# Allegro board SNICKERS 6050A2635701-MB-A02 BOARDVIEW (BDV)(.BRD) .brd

Outline 330.05 x 164 mm; copper layers: TOP, L2, L3, L4, L5, L6, L7, BOTTOM. Coordinates in mm from the lower left corner of the outline.

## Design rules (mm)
net group 3V3DS_PG: nets 3V3DS_PG UNNAMED_17_CSC0402_I437_A
net group 4-20: nets CL_RST#1 THRMTRIP#
net group 10-10: nets DMIC_CLK DMIC_DAT
net group 8051_TX_LED_PWRSTBY#: nets 8051_TX_LED_PWRSTBY# LED_PWRSTBY#
net group ADP_PRES: nets UNNAMED_5_BQ24736RGRR_I30_CMSRC UNNAMED_6_COMPARATOR_I63_1
net group AMP_PD: nets AMP_PD UNNAMED_54_DB3X313J0L_I631_2
net group APWROK: nets APWROK PCH_PWROK
net group AZ_R3S_SDOUT: nets HDA_SDO_R UNNAMED_27_NMOS_I61_S
net group BAT_GRNLED#: nets BAT_GRNLED# UNNAMED_27_LBSS84LT1G_I270_G
net group CFG<3>: nets CFG<3> MSR_ENABLE_N
net group CLK_PCIE3_D: nets CLK_PCIE3_DN CLK_PCIE3_DP
net group CLK_R3S_DEBUG: nets CLK_R3S_TPM CLK_TPM_DEBUG
net group CPPWR_EN: nets CPPWR_EN UNNAMED_41_RSC0402_I206_A
net group CRT_HSYNC: nets CRT_HSYNC CRT_HSYNC_R
net group CRT_VSYNC: nets CRT_VSYNC CRT_VSYNC_R
net group DDR_PG_CTRL: nets DDR_PG_CTRL UNNAMED_32_NPNB_I568_B
net group DDR_WR_VREF01: nets DDR_WR_VREF01 UNNAMED_25_CSC0402_I269_B
net group DDR_WR_VREF02: nets DDR_WR_VREF02 UNNAMED_25_CSC0402_I270_B
net group DGND_PBN: nets P3V3AL_PB UNNAMED_57_LEDSINGLE_I235_A2
net group DP1: nets DPC_DOCK_CLK_AUX_DP DPC_DOCK_DATA_AUX_DN
net group DPB2_DOCK_D: nets DPB2_DOCK_DN DPB2_DOCK_DP
net group DPB3_DOCK_D: nets DPB3_DOCK_DN DPB3_DOCK_DP
net group DPC0_DOCK_D: nets DPC0_DOCK_DN DPC0_DOCK_DP
net group DPC1_DOCK_D: nets DPC1_DOCK_DN DPC1_DOCK_DP
net group EN_1V2A: nets EN_1V2A SLP_S4#_3R
net group FPR_OFF: nets FPR_OFF FPR_OFF_GPIO11
net group GPU_THRM_DMINUS: nets GPU_THRM_DMINUS GPU_THRM_DPLUS
net group HDD_HALTLED: nets HDD_HALTLED HDD_HALTLED_R
net group HP_AMP_PD#: nets HP_AMP_PD# UNNAMED_54_NMOS_I641_D
net group HP_OUT_L1: nets UNNAMED_55_CSC0402_I514_A UNNAMED_55_HPA022642RTJ_I496_LE
net group HP_OUT_R1: nets UNNAMED_55_CSC0402_I529_A UNNAMED_55_HPA022642RTJ_I496_RI
net group HUB_XTAL_IN: nets HUB_XTAL_IN HUB_XTAL_OUT
net group ISO_PREP#: nets ISO_PREP# UNNAMED_26_CL8064701477702SR170
net group LAN_DIS#: nets LAN_DIS# UNNAMED_49_NPND_I463_B
net group LED_3S_LANACT#: nets LED_3S_LANACT# UNNAMED_49_I218LM_I128_27
net group LED_3S_LANLINK#: nets LED_3S_LANLINK# LED_3S_LANLINK#_R
net group LINE_OUT_DET: nets LINE_OUT_DET UNNAMED_54_ALC3228CG_I513_SEN_1
net group LVDS_VDD_EN: nets LVDS_VDD_EN UNNAMED_38_CN404G_I622_6
net group MAIN_BAT_DET#: nets MAIN_BAT_DET# UNNAMED_16_BP02083B24B19H_I11_2
net group MSATA_DET#: nets MSATA_DET# UNNAMED_40_APCI0020P001A01_I3_2
net group NUM_LOCK_LED#: nets NUM_LOCK_LED# UNNAMED_47_CN342G_I454_5
net group ON_OFF#1: nets ON_OFF#1 PWRBTN#
net group P3V3S_SM_AB: nets P3V3S_SM_AB UNNAMED_58_AU9542B55GBSGR_I52_1
net group P3V3S_SSD: nets P3V3S_SSD UNNAMED_40_APCI0020P001A01_I375
net group P5V0DS_SM: nets P5V0S_SM UNNAMED_58_CN152G_I567_12
net group PCIE_RX6_L0_C_D: nets PCIE_RX6_L0_C_DN PCIE_RX6_L0_C_DP
net group PM_SLP_A#: nets PM_SLP_A# UNNAMED_18_DB3X313J0L_I216_1
net group PR_AOUT_L_DOCK: nets PR_AOUT_L_DOCK UNNAMED_55_HPA022642RTJ_I457_HP
net group PR_AOUT_R_DOCK: nets PR_AOUT_R_DOCK UNNAMED_55_HPA022642RTJ_I457__1
net group PVSIM: nets UNNAMED_51_APCI0018P005A_I342_F WWAN_NGFF_DPR
net group PVT_MOSI: nets PVT_MOSI UNNAMED_46_MECC1322NU_I1013_GPI
net group R_SPI_WP#: nets R_SPI_WP# SPI_WP#
net group REC_MUTE_LED: nets REC_MUTE_LED UNNAMED_47_CN342G_I454_2
net group RSMRST#: nets RSMRST# UNNAMED_46_MECC1322NU_I1013_G_2
net group SCAN_3S_IN: nets SCAN_3S_IN<4> SCAN_3S_IN<7>
net group SCAN_3S_IN<0>: nets SCAN_3S_IN<0> SCAN_3S_IN<1>
net group SCAN_3S_IN<2>: nets SCAN_3S_IN<2> SCAN_3S_IN<3>
net group SCAN_3S_IN<5>: nets SCAN_3S_IN<5> SCAN_3S_IN<6>
net group SCAN_3S_OUT<1>: nets SCAN_3S_OUT<1> SPI_CS0#_FLH_R6_R
net group SCAN_3S_OUT<2>: nets SCAN_3S_OUT<2> SPI_SO_FLH_R6_R
net group SCAN_3S_OUT<3>: nets SCAN_3S_OUT<3> SPI_SI_FLH_R6_R
net group SCL_BAT_CHG: nets SCL_BAT_CHG UNNAMED_16_BP02083B24B19H_I11_1
net group SDA_BAT_CHG: nets SDA_BAT_CHG UNNAMED_16_BP02083B24B19H_I112_
net group UIM_CD: nets UIM_CD UIM_DATA
net group UNNAMED_5_BQ24736RGRR_I30_ACDRV: nets UNNAMED_5_BQ24736RGRR_I30_ACDRV UNNAMED_5_NMOS4D3S_I34_G
net group UNNAMED_5_BQ24736RGRR_I30_ACN: nets UNNAMED_5_BQ24736RGRR_I30_ACN UNNAMED_5_BQ24736RGRR_I30_ACP
net group UNNAMED_9_AOZ1268QI02_I10_22: nets UNNAMED_9_AOZ1268QI02_I10_AIN UNNAMED_9_AOZ1268QI02_I10_TON
net group UNNAMED_10_AOZ1268QI02_I13_22: nets UNNAMED_10_AOZ1268QI02_I13_AIN UNNAMED_10_AOZ1268QI02_I13_TON
net group UNNAMED_15_CSC0402_I258_B: nets UNNAMED_15_CSC0402_I258_B UNNAMED_15_NMOSDUALC_I254_D2
net group UNNAMED_19_502710040N001_I72_4: nets UNNAMED_19_502710040N001_I72_4 UNNAMED_19_NMOSDUALC_I66_D1
net group UNNAMED_36_CSC0402_I612_B: nets UNNAMED_36_CSC0402_I612_B UNNAMED_36_CSC0402_I615_B
net group UNNAMED_41_CSC0402_I692_A: nets UNNAMED_41_CSC0402_I692_A UNNAMED_41_DB3X313J0L_I691_3
net group UNNAMED_45_HP3DC2TR_I54_INT2: nets UNNAMED_45_HP3DC2TR_I54_INT2 UNNAMED_45_NMOS_I80_G
net group UNNAMED_50_CSC0402_I241_B: nets UNNAMED_50_CSC0402_I241_B UNNAMED_50_RSC0402_I190_B
net group UNNAMED_54_ALC3228CG_I513_CBN: nets UNNAMED_54_ALC3228CG_I513_CBN UNNAMED_54_ALC3228CG_I513_CBP
net group UNNAMED_55_CSC0402_I466_A: nets UNNAMED_55_CSC0402_I466_A UNNAMED_55_CSC0402_I466_B
net group UNNAMED_55_CSC0402_I497_A: nets UNNAMED_55_CSC0402_I497_A UNNAMED_55_CSC0402_I497_B
net group UNNAMED_55_CSC0402_I505_A: nets UNNAMED_55_CSC0402_I505_A UNNAMED_55_CSC0402_I505_B
net group UNNAMED_55_CSC0402_I516_A: nets UNNAMED_55_CSC0402_I516_A UNNAMED_55_CSC0402_I516_B
net group UNNAMED_57_CSC0402_I213_A: nets UNNAMED_57_CSC0402_I213_A UNNAMED_57_NMOS_I256_D
net group USB30_D_RX2_D: nets USB30_D_RX2_DN USB30_D_RX2_DP
net group USB30_RX0_D: nets USB30_RX0_DN USB30_RX0_DP
net group USB30_TX0_D: nets USB30_TX0_DN USB30_TX0_DP
net group USB_P0_D: nets USB_P0_DN USB_P0_DP
net group USB_P2_D: nets USB_P2_DN USB_P2_DP
net group USB_P4_D: nets USB_P4_DN USB_P4_DP
net group WWAN_OFF#: nets UNNAMED_51_CSC0402_I358_B WWAN_OFF#
net group 1V5S_PG: nets 1V5S_PG UNNAMED_18_COMPARATOR2_I225_ UNNAMED_18_COMPARATOR2_I226_ UNNAMED_18_CSC0402_I9_A UNNAMED_18_CSC0402_I27_A
net group 4-10: nets ADP_PRES ADP_PRES_OUT BKLT_EN BT_OFF BUF_PLT_RST# CLKREQ_PCIE3_N CLKREQ_PCIE4_N CLKREQ_PCIE4_R_N CPU_PROCHOT# CPU_PROCHOT#_R DDR3_DRAMRST# DDR3_DRAMRST#_CPU DEVSLP0 DEVSLP1 DOCK_ID1 DPB_DOCK_CA_DET DPB_DOCK_HPD DPB_HPD DPB_PORT_CA_DET DPB_PORT_HPD DPC_DOCK_CA_DET DPC_DOCK_HPD DPC_HPD DPC_PORT_CA_DET DPC_PORT_HPD DPWROK EDP_HPD# EN_1V05A EN_1V5S EN_VRPVDDQ EN_VRPVTT FPR_LOCK# GPS_XMIT_OFF# H_PECI INTRUDER# INV_PWM JTAG_RST# KBC_PROCHOT KBC_PWR_ON L_BKLT_EN LANLINK_STATUS LID_SW#_3 LINE_IN_SENSE LINE_OUT_SENSE MPHY_PRW_EN NFC_INT NFC_RST# NIC_XTAL_IN NIC_XTAL_OUT NMI_SMI_DBG# ON_OFF# OSC_IN OSC_OUT PCI_3S_CLKRUN# PCI_3S_SERIRQ PCIE_WAKE# PLT_RST# PM_PWROK PWM_3S_FAN# PWR_BTN_OUT# PWR_GOOD_3 RUNSCI_EC# SLP_A SLP_LAN# SLP_S3_5R SLP_S5#_3R THERM# THERM_SCI# VCC1_POR#_3 VCCSENSE VCCST_PWRGD VSSSENSE WLAN_OFF WLAN_TRANSMIT_OFF#
net group 8051_RX_CAPS_LED#: nets 8051_RX_CAPS_LED# CAPS_LED# UNNAMED_47_CN342G_I454_3
net group A_3S_ICHSPKR: nets A_3S_ICHSPKR PCBEEP PCBEEP_IC_C
net group A_LINEINL: nets UNNAMED_54_CSC0603_I579_B
net group A_LINEINR: nets UNNAMED_54_CSC0603_I578_B
net group A_MIC: nets COMBO_GPI EXT_MIC_JACK MIC_BIAS UNNAMED_54_ALC3228CG_I513_LINE1 UNNAMED_55_2SJ3005001211_I441_7 UNNAMED_55_CSC0402_I594_B UNNAMED_55_CSC0402_I599_A UNNAMED_55_CSC0603_I604_A
net group ADP_A_ID: nets ADP_A_ID LIMIT_SIGNAL LIMIT_SIGNAL_100R UNNAMED_6_NMOS_I73_D UNNAMED_6_PNPA_I55_E UNNAMED_46_CSC0402_I309_A
net group ADP_DET: nets ADP_DET UNNAMED_5_BQ24736RGRR_I30_ACDET UNNAMED_5_CSC0402_I48_B UNNAMED_5_NMOSDUALC_I46_D2 UNNAMED_8_CSC0402_I5_A UNNAMED_46_CSC0402_I625_B VBIAS VOLTAGE_ADC
net group AUDIO-B: nets A_LINEINL A_LINEINL_DOCK A_LINEINR A_LINEINR_DOCK A_MIC HP_OUT_L1 HP_OUT_R1
net group AUDIO-C: nets SPK_OUT_L_DN SPK_OUT_L_DP SPK_OUT_R_DN SPK_OUT_R_DP
net group AZ_R3S_BITCLK: nets UNNAMED_27_CL8064701477702SR170
net group AZ_R3S_RST#: nets A_SD# SPKR_EN_AB UNNAMED_27_CL8064701477702SR1_1 UNNAMED_54_DB3X313J0L_I629_2
net group AZ_R3S_SDIN0: nets UNNAMED_54_ALC3228CG_I513_SDATA
net group AZ_R3S_SYNC: nets UNNAMED_27_CL8064701477702SR1_2
net group BUF_PLT_RST#: nets UNNAMED_48_RSC0402_I170_B UNNAMED_51_APCI0018P005A_I342_R XDP_RST_R_N
net group CFG: nets CFG<0> CFG<1> CFG<2> CFG<4> CFG<5> CFG<6> CFG<7> CFG<8> CFG<9> CFG<10> CFG<11> CFG<12> CFG<13> CFG<14> CFG<15> CFG<16> CFG<17> CFG<18> CFG<19>
net group CLK-PCI: nets CLK_KBC_SIO CLK_R3S_DEBUG CLK_R3S_KBPCI
net group CRT_B: nets VGA_B_L2
net group CRT_G: nets VGA_G_L2
net group CRT_R: nets VGA_R_L2
net group CURRENT_ADC: nets CURRENT_ADC ICS UNNAMED_46_CSC0402_I856_A
net group DGND_SYS1: nets P3V3S_CAM UNNAMED_64_BEADSINGLE_I40_INA UNNAMED_64_RSC0402_I32_B UNNAMED_64_RSC0402_I34_A
net group DMIC_CLK: nets UNNAMED_54_ALC3228CG_I513_GPIO0
net group DPB_DOCK: nets DPB0_DOCK_DN DPB0_DOCK_DP DPB1_DOCK_DN DPB1_DOCK_DP
net group EN_3V: nets EN_3V UNNAMED_7_CSC0402_I69_B VRA3V3A_VCC
net group EN_5V: nets EN_5V EN_5VLDO UNNAMED_7_CSC0402_I44_A UNNAMED_7_CSC0402_I51_B UNNAMED_9_AOZ1268QI02_I10_VCC UNNAMED_10_AOZ1268QI02_I13_VCC VRA5V0A_SNB VRA5V0A_VCC VRB5V0A_BST VRB5V0A_BST1 VRB_VDD5 VRP5V0A VRP5V0A_PH
net group EN_5V_3V: nets EN_5V_3V UNNAMED_6_COMPARATOR_I63_3 UNNAMED_15_CSC0402_I347_A UNNAMED_18_COMPARATOR2_I225__1 UNNAMED_18_COMPARATOR_I211_3 VRA3V3A_LDO
net group EN_PVCORE: nets EN_PVCORE PVCORE_PG VRAVR_ON
net group GND: nets AGND_KBC DGND_CHASSIS1 DGND_CHASSIS2 DGND_CHASSIS3
net group H_PECI: nets UNNAMED_46_MECC1322NU_I1013_G_1
net group HD: nets AZ_R3S_BITCLK AZ_R3S_RST# AZ_R3S_SDIN0 AZ_R3S_SDOUT AZ_R3S_SYNC
net group HDD_SM_HALTLED: nets HDD_SM_HALTLED HDD_STP# P3V3A_SM P3V3AL_SM P3V3S_ISCT_SM P3V3S_SM UNNAMED_58_1222Y2ST3DC302C_I436 UNNAMED_58_1222Y2ST3DC302C_I437 UNNAMED_58_1222Y2ST3DC302C_I438 UNNAMED_58_6712KF08M02L_I525_8 UNNAMED_58_CN152G_I567_15 UNNAMED_58_LEDSINGLE3PINB_I518_
net group HP_OUT_AMP_L1: nets HP_OUT_AMP_L1 UNNAMED_55_BEADSINGLE_I549_INA UNNAMED_55_HPA022642RTJ_I496_HP
net group HP_OUT_AMP_R1: nets HP_OUT_AMP_R1 UNNAMED_55_BEADSINGLE_I550_INA UNNAMED_55_HPA022642RTJ_I496__1
net group HPOUT_DET: nets HPOUT_DET LINE_IN_DET UNNAMED_54_ALC3228CG_I513_SENSE
net group I2C_CLK: nets I2C_CLK PCH_3S_SMCLK UNNAMED_36_CSC0402_I623_A
net group I2C_DATA: nets I2C_DATA PCH_3S_SMDATA UNNAMED_36_PTN3355BS_I608_17
net group INTRUDER#: nets WWAN_DET#
net group ISCT_LED#: nets ISCT_LED# MIC_VREF UNNAMED_47_NMOSDUALC_I486_G1
net group KSCAN_3S_IN: nets KSCAN_3S_IN<0> KSCAN_3S_IN<1> KSCAN_3S_IN<2> KSCAN_3S_IN<3> KSCAN_3S_IN<4> KSCAN_3S_IN<5> KSCAN_3S_IN<6> KSCAN_3S_IN<8> KSCAN_3S_IN<9> KSCAN_3S_IN<10> KSCAN_3S_IN<11> KSCAN_3S_IN<12> KSCAN_3S_IN<13> KSCAN_3S_IN<14>
net group LAN: nets TD2_DN TD2_DP TD4_DN TD4_DP
net group LPC_3S_AD: nets LPC_3S_AD<0> LPC_3S_AD<1> LPC_3S_AD<2> LPC_3S_AD<3>
net group M_A_A: nets M_A_A<0> M_A_A<1> M_A_A<2> M_A_A<3> M_A_A<4> M_A_A<5> M_A_A<6> M_A_A<7> M_A_A<8> M_A_A<9> M_A_A<10> M_A_A<11> M_A_A<12> M_A_A<13> M_A_A<14> M_A_A<15>
net group M_A_DQ: nets M_A_DQ<0> M_A_DQ<1> M_A_DQ<2> M_A_DQ<3> M_A_DQ<4> M_A_DQ<5> M_A_DQ<6> M_A_DQ<7> M_A_DQ<8> M_A_DQ<9> M_A_DQ<10> M_A_DQ<11> M_A_DQ<12> M_A_DQ<13> M_A_DQ<14> M_A_DQ<15> M_A_DQ<16> M_A_DQ<17> M_A_DQ<18> M_A_DQ<19> M_A_DQ<20> M_A_DQ<21> M_A_DQ<22> M_A_DQ<23> M_A_DQ<24> M_A_DQ<25> M_A_DQ<26> M_A_DQ<27> M_A_DQ<28> M_A_DQ<29> M_A_DQ<30> M_A_DQ<31> M_A_DQ<32> M_A_DQ<33> M_A_DQ<34> M_A_DQ<35> M_A_DQ<36> M_A_DQ<37> M_A_DQ<38> M_A_DQ<39> M_A_DQ<40> M_A_DQ<41> M_A_DQ<42> M_A_DQ<43> M_A_DQ<44> M_A_DQ<45> M_A_DQ<46> M_A_DQ<47> M_A_DQ<48> M_A_DQ<49> M_A_DQ<50> M_A_DQ<51> M_A_DQ<52> M_A_DQ<53> M_A_DQ<54> M_A_DQ<55> M_A_DQ<56> M_A_DQ<57> M_A_DQ<58> M_A_DQ<59> M_A_DQ<60> M_A_DQ<61> M_A_DQ<62> M_A_DQ<63>
net group M_B_A: nets M_B_A<0> M_B_A<1> M_B_A<2> M_B_A<3> M_B_A<4> M_B_A<5> M_B_A<6> M_B_A<7> M_B_A<8> M_B_A<9> M_B_A<10> M_B_A<11> M_B_A<12> M_B_A<13> M_B_A<14> M_B_A<15>
net group M_B_DQ: nets M_B_DQ<0> M_B_DQ<1> M_B_DQ<2> M_B_DQ<3> M_B_DQ<4> M_B_DQ<5> M_B_DQ<6> M_B_DQ<7> M_B_DQ<8> M_B_DQ<9> M_B_DQ<10> M_B_DQ<11> M_B_DQ<12> M_B_DQ<13> M_B_DQ<14> M_B_DQ<15> M_B_DQ<16> M_B_DQ<17> M_B_DQ<18> M_B_DQ<19> M_B_DQ<20> M_B_DQ<21> M_B_DQ<22> M_B_DQ<23> M_B_DQ<24> M_B_DQ<25> M_B_DQ<26> M_B_DQ<27> M_B_DQ<28> M_B_DQ<29> M_B_DQ<30> M_B_DQ<31> M_B_DQ<32> M_B_DQ<33> M_B_DQ<34> M_B_DQ<35> M_B_DQ<36> M_B_DQ<37> M_B_DQ<38> M_B_DQ<39> M_B_DQ<40> M_B_DQ<41> M_B_DQ<42> M_B_DQ<43> M_B_DQ<44> M_B_DQ<45> M_B_DQ<46> M_B_DQ<47> M_B_DQ<48> M_B_DQ<49> M_B_DQ<50> M_B_DQ<51> M_B_DQ<52> M_B_DQ<53> M_B_DQ<54> M_B_DQ<55> M_B_DQ<56> M_B_DQ<57> M_B_DQ<58> M_B_DQ<59> M_B_DQ<60> M_B_DQ<61> M_B_DQ<62> M_B_DQ<63>
net group M_ODT0: nets UNNAMED_32_NMOS_I514_S
net group M_PWROK: nets M_PWROK UNNAMED_18_COMPARATOR_I211_1 UNNAMED_18_CSC0402_I96_A UNNAMED_18_CSC0402_I96_B UNNAMED_18_CSC0402_I112_A UNNAMED_18_DB3X313J0L_I217_2
net group OCP_A_IN: nets OCP_A_IN UNNAMED_5_BQ24736RGRR_I30_DLIM UNNAMED_6_NPND_I54_B UNNAMED_46_CSC0402_I857_A V_3.9K
net group P0V675M_VREF_H: nets UNNAMED_25_CSC0402_I271_B
net group P3V3_CR: nets UNNAMED_56_NMOS_I363_S
net group P3V3S_ISCT: nets P3V3S_ISCT UNNAMED_57_2322BY2ST3DC302A_I15 UNNAMED_57_2322BY2ST3DC302A_I_2 UNNAMED_57_2322BY2ST3DC302A_I_4
net group PCH_3S_SM: nets DPC_PORT_CLK_AUX_C1_DP DPC_PORT_CLK_AUX_DP DPC_PORT_DATA_AUX_C1_DN DPC_PORT_DATA_AUX_DN
net group PCI_3S_SERIRQ: nets UNNAMED_46_MECC1322NU_I1013_SER
net group PCIE_RX2_C_DN: nets PCIE_RX2_DN
net group PCIE_RX2_C_DP: nets PCIE_RX2_DP
net group PR_AOUT_L_AB: nets PR_AOUT_L_AB UNNAMED_55_CSC0603_I568_B UNNAMED_55_HPA022642RTJ_I457_LE
net group PR_AOUT_R_AB: nets PR_AOUT_R_AB UNNAMED_55_CSC0603_I569_B UNNAMED_55_HPA022642RTJ_I457_RI
net group PVPACK: nets UNNAMED_5_BQ24736RGRR_I30_BTST UNNAMED_5_CHOKE2PIN_I90_INB UNNAMED_5_CSC0402_I59_A UNNAMED_5_CSC0402_I61_A
net group PVSM_VCC_SM: nets PVSM_VCC_SM SCARDDATA UNNAMED_58_AU9542B55GBSGR_I52_2
net group PVT_SCLK: nets UNNAMED_46_MECC1322NU_I1013_G_3
net group R_SPI_HOLD#_DB: nets SPI_HOLD#_DB
net group RCOMP: nets UNNAMED_21_CL8064701477702SR1_1 UNNAMED_21_CL8064701477702SR1_2 UNNAMED_21_CL8064701477702SR170 UNNAMED_24_CL8064701477702SR170 UNNAMED_26_CL8064701477702SR1_1 UNNAMED_26_CL8064701477702SR1_2 UNNAMED_26_CL8064701477702SR1_3 UNNAMED_27_CL8064701477702SR1_3
net group SATA_RX1_C_DN: nets SATA_RX1_DN
net group SATA_RX1_C_DP: nets SATA_RX1_DP
net group SATA_TX1_C_DN: nets SATA_TX1_DN
net group SATA_TX1_C_DP: nets SATA_TX1_DP
net group SCAN_3S_OUT: nets SCAN_3S_OUT<4> SCAN_3S_OUT<5> SCAN_3S_OUT<6> SCAN_3S_OUT<7> SCAN_3S_OUT<8> SCAN_3S_OUT<9> SCAN_3S_OUT<10> SCAN_3S_OUT<11> SCAN_3S_OUT<17>
net group SCAN_3S_OUT<0>: nets SCAN_3S_OUT<0>
net group SD: nets SCARDC6 SCARDC8 SCARDCLK SCARDFCB SCARDRST SD_MMC_CD# SD_MMC_CLK SD_MMC_CMD SD_MMC_WP
net group SDDR_CLK: nets M_CLK_DDR0_DN M_CLK_DDR0_DP M_CLK_DDR1_DN M_CLK_DDR1_DP M_CLK_DDR2_DN M_CLK_DDR2_DP M_CLK_DDR3_DN M_CLK_DDR3_DP
net group SDDR_CMD: nets M_A_BS0 M_A_BS1 M_A_BS2 M_A_CAS# M_A_RAS# M_A_WE# M_B_BS0 M_B_BS1 M_B_BS2 M_B_CAS# M_B_RAS# M_B_WE#
net group SDDR_CTRL: nets M_CKE0 M_CKE1 M_CKE2 M_CKE3 M_CS#0 M_CS#1 M_CS#2 M_CS#3 M_ODT0 M_ODT1 M_ODT2 M_ODT3
net group SDDR_DQS: nets M_A_DQS0_DN M_A_DQS0_DP M_A_DQS1_DN M_A_DQS1_DP M_A_DQS3_DN M_A_DQS3_DP M_A_DQS4_DN M_A_DQS4_DP M_A_DQS5_DN M_A_DQS5_DP M_A_DQS6_DN M_A_DQS6_DP M_A_DQS7_DN M_A_DQS7_DP M_B_DQS4_DN M_B_DQS4_DP M_B_DQS5_DN M_B_DQS5_DP M_B_DQS6_DN M_B_DQS6_DP M_B_DQS7_DN M_B_DQS7_DP
net group SLP_S3#_3R: nets SLP_S3#_3R SLP_S3#_3R_DOCK SLP_S3#_3R_KBC UNNAMED_18_DB3X313J0L_I217_1
net group SLP_S4#_KBC: nets SLP_S4#_KBC UNNAMED_41_CSC0402_I174_B UNNAMED_46_MECC1322NU_I1013_ADC
net group SM: nets CRT_DDCCLK DMIC_CLK_DB DMIC_DATA_DB DPB_DDCCLK DPC_DDCCLK IM_5S_CLK IM_5S_CLK_SM IM_5S_DATA IM_5S_DATA_SM KBC_ECPH_CLK KBC_ECPH_DATA NFC_3S_SMCLK NFC_3S_SMDATA PCH_3A_SMCLK PCH_3A_SMDATA PCH_3M_SMCLK PCH_3M_SMDATA PCH_3S_SMCLK_SM PCH_3S_SMDATA_SM PCH_KBC_SMCLK PCH_KBC_SMDATA PCH_SML1CLK PCH_SML1DATA SP_CLK SP_DATA
net group SPI: nets PVT_CS# PVT_MISO PVT_MISO_R PVT_SCLK R_SPI_CLK_FLH R_SPI_CS0#_FLH R_SPI_HOLD#_DB R_SPI_SI_FLH SPI_CLK_FLH SPI_CLK_FLH_KR SPI_CLK_FLH_R6_R SPI_CS0#_FLH SPI_HOLD#_DB_R6_R SPI_SI_FLH SPI_SI_FLH_KR SPI_SO_FLH SPI_SO_FLH_R
net group SPK_OUT_L_DN: nets UNNAMED_54_CSC0402_I608_B
net group SPK_OUT_L_DP: nets UNNAMED_54_CSC0402_I609_B
net group SPK_OUT_R_DN: nets UNNAMED_54_CSC0402_I607_B
net group SPK_OUT_R_DP: nets UNNAMED_54_CSC0402_I606_B
net group UIM: nets NFC_SWP UIM_CLK UIM_RST UIM_VPP
net group UNNAMED_5_BQ24736RGRR_I30_SRN: nets UNNAMED_5_BQ24736RGRR_I30_SRN UNNAMED_5_BQ24736RGRR_I30_SRP UNNAMED_5_CSC0402_I73_A UNNAMED_5_CSC0402_I74_B
net group UNNAMED_49_CSC0603_I402_A: nets UNNAMED_49_CSC0603_I402_A UNNAMED_49_CSC0603_I402_B UNNAMED_49_CSC0603_I403_A UNNAMED_49_CSC0603_I403_B UNNAMED_49_CSC0603_I404_A UNNAMED_49_CSC0603_I404_B UNNAMED_49_CSC0603_I405_A UNNAMED_49_CSC0603_I405_B UNNAMED_49_CSCSPECIAL_I439_A
net group USB30_TX1_C_DN: nets USB30_TX1_C_DN
net group USB30_TX1_C_DP: nets USB30_TX1_C_DP
net group USB_D_P1_DN: nets USB_D_P1_L_DN
net group USB_D_P1_DP: nets USB_D_P1_L_DP
net group USB_D_P3_DN: nets USB_D_P3_L_DN
net group USB_D_P3_DP: nets USB_D_P3_L_DP
net group USB_P5_DN: nets USB_P5_L_DN
net group USB_P5_DP: nets USB_P5_L_DP
net group VCCST_PWRGD: nets VCCST_PWRGD_XDP
net group VGA_DAC: nets CRT_B CRT_G CRT_R
net group VR_SVID_ALERT#: nets UNNAMED_30_CL8064701477702SR1_4
net group VRA: nets P0V675M_VREF P0V675S_DIMM0_VREF_CA P0V675S_DIMM0_VREF_DQ P0V675S_DIMM1_VREF_DQ P1V2_CR P1V2_PHY_CR P1V2A P1V05_LAN_M_PHY P1V05_NIC P1V5_VDD P1V05A_SATA3PLL P1V05A_USB3PLL P1V05M P1V05S P1V5S P1V05S_APLLOPI P1V05S_AXCK_DCB P1V05S_SSCF100 P1V05S_VCCP P3V3_CR P3V3_RTC P3V3_TPM P3V3A P3V3AL_KBC P3V3AL_RTC_BAT P3V3D_P1V8D P3V3M P3V3M_R_RSVD P3V3S_AVDD33 P3V3S_DVDD33 P3V3S_LCDVDD P3V3S_VCC_READER P3VA_D_L P5V0DS_SM P5V0S_CRTVDD P5V0S_HDD P5V0S_KBL P15V0A PVBAT_CPU PVCCIO_OUT PVCCIO_OUT_R PVSIM PWR_DEBUG UNNAMED_14_CSD97374CQ4M_I37_4 UNNAMED_14_IDUT4PIN_I38_3 UNNAMED_14_RSC0402_I20_B UNNAMED_36_IDUTSINGLE_I650_INA UNNAMED_56_DB3X313J0L_I357_3 VADPBL VCCIOA_OUT VRA3V3A_SNB VRA3V3A_VCLK VRA5V0A_LDO VRACPU_BST1 VRACPU_BST11 VRACPU_BST12 VRACPU_COMP VRACPU_COMP1 VRACPU_CSN1 VRACPU_CSN2 VRACPU_CSN3 VRACPU_CSP1 VRACPU_CSP2 VRACPU_CSP3 VRACPU_DROOP VRACPU_IMAX VRACPU_IMON VRACPU_OCP VRACPU_PWM1 VRACPU_PWM2 VRACPU_PWM3 VRACPU_RAMP VRACPU_SKIP# VRACPU_SLEWA VRACPU_SNB1 VRACPU_THERM VRACPU_USR VRACPU_V5A VRACPU_VBAT VRACPU_VDD VRACPU_VREF VRANB669GQ_VCLK VRANB669GQ_VCLK1 VRANB669GQ_VCLK2 VRANB669GQ_VCLK3 VREF_EQ
net group VRB: nets PVADPTR PVCORE VRB3V3A_BST VRB3V3A_BST1 VRPVPACK_HG VRPVPACK_LG
net group VRP: nets VR_SVID_ALERT# VR_SVID_CLK VR_SVID_DATA VRP1V2A VRP1V2A_PH VRP1V05A VRP1V05A_PH VRP1V5S VRPPM_SLP_S0_N VRPPM_SLP_S0_N_R VRPVDDQ VRPVDDQ_PG VRPVPACK_PH VRPVTT_REF
net group VRP1V2A: nets UNNAMED_12_CSC0402_I9_B
net group VRP1V05A: nets UNNAMED_10_AOZ1268QI02_I13_BST UNNAMED_10_AOZ1268QI02_I13_FB UNNAMED_10_CSC0402_I22_A UNNAMED_10_CSC0402_I24_A
net group VRP1V5S: nets UNNAMED_11_CSC0402_I9_B
net group VRPVDDQ: nets UNNAMED_9_AOZ1268QI02_I10_BST UNNAMED_9_AOZ1268QI02_I10_FB UNNAMED_9_CSC0402_I20_A UNNAMED_9_CSC0402_I32_A

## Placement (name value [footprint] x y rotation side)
C100  1uF_6.3V_2  [CSC_100X050X040_2]  272.83 113.9 90 top
C131  0.1uF_16V_2  [CSC_100X050X040_2]  280.82 104.01 0 top
C301  2200pF_50V_2  [CSC_100X050X040_2]  284.64 97.27 0 top
C302  1uF_25V_3  [CSC_160X080X080_2]  269.27 91.04 270 top
C303  0.1uF_16V_2  [CSC_100X050X040_2]  281.72 94.22 0 top
C304  2200pF_50V_2  [CSC_100X050X040_2]  284.64 96.38 180 top
C305  0.1uF_16V_2  [CSC_100X050X040_2]  265.34 87.74 90 top
C306  2200pF_50V_2  [CSC_100X050X040_2]  284.64 98.16 0 top
C307  2200pF_50V_2  [CSC_100X050X040_2]  284.64 99.05 0 top
C308  0.1uF_16V_2  [CSC_100X050X040_2]  267.37 113.9 90 top
C310  0.1uF_16V_2  [CSC_100X050X040_2]  258.48 105.92 180 top
C311  1uF_6.3V_2  [CSC_100X050X040_2]  277.15 113.9 90 top
C312  0.1uF_16V_2  [CSC_100X050X040_2]  276.26 113.9 90 top
C313  0.1uF_16V_2  [CSC_100X050X040_2]  281.72 100.95 180 top
C314  0.1uF_16V_2  [CSC_100X050X040_2]  268.26 91.88 270 top
C315  0.1uF_16V_2  [CSC_100X050X040_2]  258.51 99.51 180 top
C316  0.1uF_16V_2  [CSC_100X050X040_2]  231.17 57.52 270 bottom
C320  0.1uF_16V_2_DY  [CSC_100X050X040_2]  230.28 57.52 270 bottom
C321  0.1uF_16V_2_DY  [CSC_100X050X040_2]  145.07 65.26 270 bottom
C335  0.1uF_16V_2_DY  [CSC_100X050X040_2]  266.22 87.74 90 top
C366  0.1uF_16V_2  [CSC_100X050X040_2]  144.18 65.26 270 bottom
C400  10pF_50V_2  [CSC_100X050X040_2]  296.45 104.51 180 top
C401  0.1uF_16V_2  [CSC_100X050X040_2]  288.41 108.1 270 top
C402  1uF_6.3V_2  [CSC_100X050X040_2]  286.54 104.76 90 top
C403  0.1uF_16V_2  [CSC_100X050X040_2]  297.55 111.86 0 top
C404  10pF_50V_2  [CSC_100X050X040_2]  294.8 104.51 0 top
C407  0.1uF_16V_2  [CSC_100X050X040_2]  288.54 115.07 270 top
C408  0.1uF_16V_2  [CSC_100X050X040_2]  289.43 115.07 270 top
C409  22uF_6.3V_5  [CSC_200X125X130_2]  297.03 105.78 0 top
C470  0.01uF_100V_3  [CSC_160X080X080_2]  312.45 100.19 270 top
C471  0.01uF_100V_3  [CSC_160X080X080_2]  312.96 95.49 0 top
C472  0.01uF_100V_3  [CSC_160X080X080_2]  312.96 93.33 0 top
C473  0.01uF_100V_3  [CSC_160X080X080_2]  312.96 90.41 0 top
C474  100PF_3000V  [CSC_460X200X180_2]  310.67 85.58 270 top
C475  0.1uF_16V_2  [CSC_100X050X040_2]  298.61 101.46 180 top
C476  0.1uF_16V_2  [CSC_100X050X040_2]  298.61 100.06 180 top
C477  0.1uF_16V_2  [CSC_100X050X040_2]  302.93 87.49 270 top
C478  0.1uF_16V_2  [CSC_100X050X040_2]  303.82 87.49 270 top
C479  1uF_6.3V_2  [CSC_100X050X040_2]  304.71 87.49 270 top
C486  0.1uF_25V_2  [CSC_100X050X040_2]  314.87 106.92 180 top
C501  10uF_6.3V_3  [CSC_160X080X080_2]  303.44 70.22 90 top
C502  10uF_6.3V_3  [CSC_160X080X080_2]  296.53 62.85 180 top
C503  0.1uF_16V_2  [CSC_100X050X040_2]  296.32 59.04 180 bottom
C504  2.2uF_6.3V_3  [CSC_160X080X090_2]  306.61 54.34 0 top
C505  0.1uF_16V_2  [CSC_100X050X040_2]  296.78 61.83 180 top
C506  10uF_6.3V_3  [CSC_160X080X080_2]  306.36 66.08 90 top
C507  0.1uF_16V_2  [CSC_100X050X040_2]  305.34 65.77 90 top
C508  10uF_6.3V_3  [CSC_160X080X080_2]  297.21 65.64 90 top
C509  0.1uF_16V_2  [CSC_100X050X040_2]  302.93 66.28 90 top
C510  10uF_6.3V_3  [CSC_160X080X080_2]  303.94 66.41 90 top
C511  0.1uF_16V_2  [CSC_100X050X040_2]  306.36 57.39 0 top
C512  10uF_6.3V_3  [CSC_160X080X080_2]  306.74 56.37 0 top
C513  10uF_6.3V_3  [CSC_160X080X080_2]  303.69 54.47 270 top
C514  4.7uF_6.3V_3  [CSC_160X080X080_2]  299.63 54.47 270 top
C515  0.1uF_16V_2  [CSC_100X050X040_2]  298.36 65.64 90 top
C516  2.2uF_6.3V_3  [CSC_160X080X090_2]  308.26 64.12 0 top
C517  0.1uF_16V_2  [CSC_100X050X040_2]  306.61 55.36 0 top
C518  0.1uF_16V_2  [CSC_100X050X040_2]  296.2 57.14 180 top
C519  100pF_50V_2  [CSC_100X050X040_2]  294.55 58.61 90 top
C521  2.2uF_6.3V_3  [CSC_160X080X090_2]  308.13 65.52 0 top
C523  10pF_50V_2_DY  [CSC_100X050X040_2]  171.1 102.35 180 bottom
C526  4.7uF_6.3V_3  [CSC_160X080X080_2]  302.55 54.47 270 top
C527  0.1uF_16V_2  [CSC_100X050X040_2]  289.21 62.85 270 top
C529  0.1uF_16V_2  [CSC_100X050X040_2]  302.42 70.72 90 top
C532  1uF_6.3V_2  [CSC_100X050X040_2]  299.5 72.76 90 top
C550  1uF_6.3V_2  [CSC_100X050X040_2]  304.45 71.87 180 top
C551  0.1uF_16V_2  [CSC_100X050X040_2]  304.45 72.76 180 top
C552  1uF_6.3V_2  [CSC_100X050X040_2]  304.45 73.65 0 top
C553  2.2uF_6.3V_3  [CSC_160X080X090_2]  304.32 74.92 180 top
C554  1uF_6.3V_2  [CSC_100X050X040_2]  309.66 77.2 90 top
C555  0.1uF_16V_2  [CSC_100X050X040_2]  308.77 77.2 90 top
C560  10uF_6.3V_3  [CSC_160X080X080_2]  305.24 67.73 90 top
C561  10uF_6.3V_3  [CSC_160X080X080_2]  308.13 66.66 0 top
C562  1uF_6.3V_2  [CSC_100X050X040_2]  309.91 64.76 90 top
C563  0.1uF_16V_2  [CSC_100X050X040_2]  310.8 64.76 90 top
C564  1uF_6.3V_2  [CSC_100X050X040_2]  311.69 64.76 270 top
C565  2.2uF_6.3V_3  [CSC_160X080X090_2]  312.96 65.14 90 top
C566  1uF_6.3V_2  [CSC_100X050X040_2]  312.81 57.39 180 top
C567  0.1uF_16V_2  [CSC_100X050X040_2]  312.07 56.5 180 top
C569  1uF_6.3V_2  [CSC_100X050X040_2]  308.26 61.45 180 top
C570  1uF_6.3V_2  [CSC_100X050X040_2]  308.26 60.18 180 top
C572  1uF_6.3V_2  [CSC_100X050X040_2]  306.23 63.23 0 top
C573  1uF_6.3V_2  [CSC_100X050X040_2]  306.61 59.68 180 top
C574  100pF_50V_2  [CSC_100X050X040_2]  308.9 53.07 0 top
C575  100pF_50V_2  [CSC_100X050X040_2]  310.55 53.07 180 top
C601  0.033uF_16V_2  [CSC_100X050X040_2]  318.93 6.34 270 bottom
C602  0.033uF_16V_2  [CSC_100X050X040_2]  318.93 11.42 270 bottom
C603  220pF_50V_2  [CSC_100X050X040_2]  324.39 9.64 90 bottom
C604  1uF_6.3V_2  [CSC_100X050X040_2]  236.36 47.36 180 bottom
C605  4.7uF_6.3V_3  [CSC_160X080X080_2]  303.56 52.69 180 top
C612  15pF_50V_2_DY  [CSC_100X050X040_2]  285.66 53.71 0 bottom
C613  2.2uF_6.3V_2_DY  [CSC_100X050X040_2]  292.87 56.19 0 bottom
C614  0.1uF_16V_2_DY  [CSC_100X050X040_2]  293.38 55.04 0 bottom
C615  0.1uF_16V_2_DY  [CSC_100X050X040_2]  293.38 53.14 0 bottom
C616  100pF_50V_2_DY  [CSC_100X050X040_2]  285.66 54.72 180 bottom
C617  68pF_50V_2_DY  [CSC_100X050X040_2]  288.2 57.9 0 bottom
C627  2.2uF_10V_3  [CSC_160X080X080_2]  287.69 56.25 180 bottom
C640  1000PF_50V_2  [CSC_100X050X055_2]  299.37 66.28 90 top
C641  1000PF_50V_2  [CSC_100X050X055_2]  300.26 66.28 90 top
C642  1000PF_50V_2  [CSC_100X050X055_2]  301.15 66.28 90 top
C643  1000PF_50V_2  [CSC_100X050X055_2]  302.04 66.28 90 top
C650  1000PF_50V_2  [CSC_100X050X055_2]  198.01 43.8 0 bottom
C651  4.7uF_6.3V_3  [CSC_160X080X080_2]  198.01 44.82 0 bottom
C652  1000PF_50V_2  [CSC_100X050X055_2]  243.47 46.59 180 bottom
C653  4.7uF_6.3V_3  [CSC_160X080X080_2]  240.82 47.48 180 bottom
C800  0.1uF_16V_2  [CSC_100X050X040_2]  287.31 68.57 180 top
C801  4.7uF_6.3V_3  [CSC_160X080X080_2]  286.16 67.55 180 top
C802  1uF_6.3V_2  [CSC_100X050X040_2]  290.48 67.85 180 top
C803  0.1uF_16V_2  [CSC_100X050X040_2]  297.34 73.39 0 top
C804  10uF_6.3V_3  [CSC_160X080X080_2]  284.13 68.69 270 top
C805  0.1uF_16V_2  [CSC_100X050X040_2]  287.69 70.55 180 top
C806  0.1uF_16V_2  [CSC_100X050X040_2]  287.18 71.49 180 top
C807  4.7uF_6.3V_3  [CSC_160X080X080_2]  297.85 74.41 0 top
C808  10uF_6.3V_3  [CSC_160X080X080_2]  297.24 67.42 0 top
C810  0.1uF_16V_2  [CSC_100X050X040_2]  295.1 62.22 0 bottom
C811  0.1uF_16V_2  [CSC_100X050X040_2]  289.59 73.01 0 top
C813  0.1uF_16V_2  [CSC_100X050X040_2]  289.72 73.9 0 top
C1000  10uF_6.3V_3  [CSC_160X080X080_2]  243.87 93.46 270 top
C1001  0.1uF_16V_2  [CSC_100X050X040_2]  242.86 93.46 270 top
C1301  0.1uF_16V_2  [CSC_100X050X040_2]  306.1 131.43 180 top
C1303  10uF_6.3V_3  [CSC_160X080X080_2]  308.13 112.13 90 top
C1304  0.1uF_16V_2  [CSC_100X050X040_2]  307.12 112 90 top
C1305  0.01uF_50V_2  [CSC_100X050X040_2]  304.71 133.72 180 top
C1307  4.7uF_6.3V_3  [CSC_160X080X080_2]  305.72 132.7 180 top
C1308  0.1uF_16V_2_DY  [CSC_100X050X055_2]  303.82 128.64 90 top
C1402  0.1uF_16V_2_DY  [CSC_100X050X040_2]  261.14 80 0 bottom
C1405  18pF_50V_2_DY  [CSC_100X050X040_2]  253.14 80.63 90 top
C1413  0.01uF_50V_2  [CSC_100X050X040_2]  257.33 74.53 0 bottom
C1414  0.1uF_16V_2  [CSC_100X050X040_2]  257.33 75.42 0 bottom
C1415  4.7uF_6.3V_3  [CSC_160X080X080_2]  257.03 76.47 0 bottom
C1451  0.1uF_16V_2  [CSC_100X050X040_2]  255.18 79.87 90 top
C1452  4.7uF_6.3V_3  [CSC_160X080X080_2]  256.32 80 90 top
C1453  18pF_50V_2_DY  [CSC_100X050X040_2]  250.6 80.63 90 top
C1700  68pF_50V_2  [CSC_100X050X040_2]  98.58 87.36 90 bottom
C1701  4.7uF_6.3V_3  [CSC_160X080X080_2]  97.57 87.11 90 bottom
C1702  0.01uF_50V_2  [CSC_100X050X040_2]  76.61 82.41 0 top
C1703  0.01uF_50V_2  [CSC_100X050X040_2]  76.61 83.3 0 top
C1704  0.01uF_50V_2  [CSC_100X050X040_2]  71.15 82.41 0 top
C1705  0.01uF_50V_2  [CSC_100X050X040_2]  71.15 81.52 0 top
C1956  4.7uF_6.3V_3  [CSC_160X080X080_2]  290.35 90.54 180 top
C2200  0.1uF_16V_2  [CSC_100X050X040_2]  283.37 54.98 180 bottom
C2201  4.7uF_6.3V_3  [CSC_160X080X080_2]  283.62 53.96 180 bottom
C2250  0.1uF_16V_2  [CSC_100X050X040_2]  111.41 121.91 90 top
C2251  4.7uF_6.3V_3  [CSC_160X080X080_2]  110.4 121.91 90 top
C2255  0.1uF_16V_2  [CSC_100X050X040_2]  113.32 120.13 90 top
C2256  1uF_6.3V_2  [CSC_100X050X040_2]  112.3 121.91 90 top
C2401  22uF_6.3V_5  [CSC_200X125X130_2]  314.23 73.52 90 top
C2402  0.1uF_16V_2  [CSC_100X050X040_2]  313.98 64.88 90 top
C2404  0.1uF_16V_2  [CSC_100X050X040_2]  313.6 68.57 0 top
C2405  0.1uF_16V_2  [CSC_100X050X040_2]  313.6 67.68 0 top
C2406  0.1uF_16V_2  [CSC_100X050X040_2]  316.32 49.73 270 top
C2407  0.1uF_16V_2  [CSC_100X050X040_2]  315.43 49.73 270 top
C2408  0.1uF_16V_2  [CSC_100X050X040_2]  316.77 38.34 0 bottom
C2411  22uF_6.3V_5  [CSC_200X125X130_2]  316.64 37.07 0 bottom
C2412  1uF_6.3V_2  [CSC_100X050X040_2]  308.26 86.98 90 top
C2413  22uF_6.3V_5_DY  [CSC_200X125X130_2]  324.52 38.72 270 bottom
C2414  1uF_6.3V_2  [CSC_100X050X040_2]  323.25 37.96 270 bottom
C2415  22UF_6.3V_3_DY  [CSC_160X080X090_2]  306.99 86.85 90 top
C2500  0.1uF_16V_2  [CSC_100X050X040_2]  42.96 52.69 270 bottom
C2501  0.1uF_16V_2  [CSC_100X050X040_2]  42.07 52.69 270 bottom
C2503  0.1uF_16V_2  [CSC_100X050X040_2]  41.18 52.69 90 bottom
C2512  100uF_6.3V  [CST_320X160X180_2_245]  37.5 83.81 180 top
C2513  0.1uF_16V_2  [CSC_100X050X040_2]  46.9 81.52 0 bottom
C2514  0.1uF_16V_2  [CSC_100X050X040_2]  42.45 77.84 180 bottom
C2550  15pF_50V_2  [CSC_100X050X040_2]  266.35 55.36 270 top
C2551  4.7uF_6.3V_3  [CSC_160X080X080_2]  273.84 56.37 90 bottom
C2552  4.7uF_6.3V_3  [CSC_160X080X080_2]  278.04 66.91 90 top
C2553  0.1uF_16V_2  [CSC_100X050X040_2]  276.64 53.58 180 bottom
C2554  0.1uF_16V_2  [CSC_100X050X040_2]  267.93 52.82 270 top
C2555  0.1uF_16V_2  [CSC_100X050X040_2]  277.02 66.79 90 top
C2556  0.1uF_16V_2  [CSC_100X050X040_2]  265.84 62.22 180 top
C2557  0.1uF_16V_2  [CSC_100X050X040_2]  276 59.68 180 bottom
C2558  0.1uF_16V_2  [CSC_100X050X040_2]  276 58.79 180 bottom
C2559  0.1uF_16V_2  [CSC_100X050X040_2]  275.11 53.2 270 top
C2560  0.1uF_16V_2  [CSC_100X050X040_2]  272.12 53.2 270 top
C2561  0.1uF_16V_2  [CSC_100X050X040_2]  271.23 53.2 270 top
C2562  0.1uF_16V_2  [CSC_100X050X040_2]  275.37 57.39 180 bottom
C2563  0.1uF_16V_2  [CSC_100X050X040_2]  265.84 63.1 180 top
C2564  0.1uF_16V_2  [CSC_100X050X040_2]  265.84 59.55 180 top
C2566  15pF_50V_2  [CSC_100X050X040_2]  266.35 53.71 90 top
C2567  0.1uF_16V_2  [CSC_100X050X040_2]  265.84 60.44 0 top
C2568  0.1uF_16V_2  [CSC_100X050X040_2]  265.84 61.33 0 top
C2569  0.1uF_16V_2  [CSC_100X050X040_2]  265.84 57.77 0 top
C2570  0.1uF_16V_2  [CSC_100X050X040_2]  265.84 58.66 0 top
C2575  100pF_50V_2_DY  [CSC_100X050X040_2]  265.84 64.12 180 top
C2578  0.01uF_50V_2  [CSC_100X050X040_2]  265.84 66.53 0 top
C2582  0.1uF_16V_2  [CSC_100X050X040_2]  269.02 71.61 270 top
C2583  0.1uF_16V_2  [CSC_100X050X040_2]  271.43 71.23 90 top
C2584  0.1uF_16V_2  [CSC_100X050X040_2]  267.75 66.66 90 top
C2590  0.1uF_16V_2_DY  [CSC_100X050X055_2]  256.83 59.04 90 bottom
C2950  1000PF_50V_2  [CSC_100X050X055_2]  251.62 108.32 270 top
C2951  0.068uF_10V_2  [CSC_100X050X040_2]  254.3 114.64 90 top
C2952  3300pF_50V_2  [CSC_100X050X040_2]  247.81 109.08 270 top
C2970  CSC0402_DY  [CSC_100X050X040_2]  297.69 121.74 270 top
C2971  10uF_6.3V_3  [CSC_160X080X080_2]  293.15 122.03 90 top
C2990  10uF_6.3V_3  [CSC_160X080X080_2]  137.32 81.9 0 bottom
C2994  22uF_6.3V_5_DY  [CSC_200X125X130_2]  137.83 90.92 90 bottom
C2995  22uF_6.3V_5_DY  [CSC_200X125X130_2]  139.48 90.92 90 bottom
C3003  4.7uF_6.3V_3  [CSC_160X080X080_2]  104.68 108.82 180 top
C3006  1uF_6.3V_2  [CSC_100X050X040_2]  102.65 108.82 0 top
C3009  0.1uF_16V_2  [CSC_100X050X040_2]  109.51 113.4 0 top
C3010  0.1uF_16V_2  [CSC_100X050X040_2]  109.51 112.51 0 top
C3011  0.1uF_16V_2  [CSC_100X050X040_2]  109.51 111.62 0 top
C3012  0.1uF_16V_2  [CSC_100X050X040_2]  109.51 110.73 0 top
C3013  0.1uF_16V_2  [CSC_100X050X040_2]  109.51 109.84 0 top
C3014  0.1uF_16V_2  [CSC_100X050X040_2]  109.51 108.95 0 top
C3015  680pF_50V_2_DY  [CSC_100X050X040_2]  116.24 120.25 0 top
C3051  12pF_50V_2  [CSC_100X050X040_2]  39.53 65.01 270 top
C3052  12pF_50V_2  [CSC_100X050X040_2]  39.53 67.3 270 top
C3053  12pF_50V_2  [CSC_100X050X040_2]  39.53 69.71 270 top
C3054  12pF_50V_2  [CSC_100X050X040_2]  36.99 65.01 270 top
C3055  12pF_50V_2  [CSC_100X050X040_2]  36.99 67.3 270 top
C3056  12pF_50V_2  [CSC_100X050X040_2]  36.99 69.71 270 top
C3058  0.1uF_16V_2  [CSC_100X050X040_2]  38.26 76.44 90 bottom
C3059  CSC0402_DY  [CSC_100X050X040_2]  84.09 81.13 0 top
C3060  CSC0402_DY  [CSC_100X050X040_2]  82.41 81.18 0 top
C3061  0.01uF_50V_2  [CSC_100X050X040_2]  83.47 89.27 270 bottom
C3062  0.1uF_16V_2  [CSC_100X050X040_2]  84.36 89.27 270 bottom
C3065  1uF_6.3V_2  [CSC_100X050X040_2]  93.28 91.72 90 bottom
C3066  0.01uF_50V_2  [CSC_100X050X040_2]  91.89 91.72 90 bottom
C3067  0.1uF_16V_2  [CSC_100X050X040_2]  93.25 86.6 0 top
C3068  2.2uF_6.3V_2_DY  [CSC_100X050X040_2]  93.89 86.87 0 bottom
C3069  0.01uF_50V_2_DY  [CSC_100X050X040_2]  88.41 91.87 180 bottom
C3070  2.2uF_6.3V_2_DY  [CSC_100X050X040_2]  90.58 93.97 180 bottom
C3071  15pF_50V_2  [CSC_100X050X040_2]  93.72 84.46 90 top
C3072  15pF_50V_2  [CSC_100X050X040_2]  93.72 82.81 270 top
C3073  1uF_6.3V_2_DY  [CSC_100X050X040_2]  79.79 90.79 180 top
C3074  0.1uF_16V_2_DY  [CSC_100X050X040_2]  78.26 89.14 90 top
C3075  0.1uF_16V_2  [CSC_100X050X040_2]  95.55 92.84 180 bottom
C3076  0.1uF_16V_2  [CSC_100X050X040_2]  95.55 93.75 180 bottom
C3077  0.1uF_16V_2  [CSC_100X050X040_2]  85.72 91.44 270 bottom
C3078  0.1uF_16V_2  [CSC_100X050X040_2]  87.92 92.7 180 top
C3079  0.1uF_16V_2  [CSC_100X050X040_2]  87.92 93.58 180 top
C3080  0.1uF_16V_2  [CSC_100X050X040_2]  84.11 91.81 180 top
C3081  0.1uF_16V_2  [CSC_100X050X040_2]  84.11 92.7 180 top
C3085  0.1uF_16V_2  [CSC_100X050X040_2]  91.05 87 0 top
C3087  0.1uF_16V_2_DY  [CSC_100X050X040_2]  86.14 83.42 0 bottom
C3088  1uF_6.3V_2  [CSC_100X050X040_2]  90.58 93.08 0 bottom
C3089  0.01uF_50V_2  [CSC_100X050X040_2]  91.46 92.59 0 top
C3090  1uF_6.3V_2  [CSC_100X050X040_2]  91.23 89.51 0 bottom
C3091  0.01uF_50V_2  [CSC_100X050X040_2]  91.23 88.6 0 bottom
C3092  4.7uF_6.3V_3  [CSC_160X080X080_2]  93.89 88.01 0 bottom
C3093  0.1uF_16V_2  [CSC_100X050X040_2]  80.93 83.17 180 top
C3094  1uF_6.3V_2_DY  [CSC_100X050X040_2]  80.04 85.33 270 bottom
C3300  0.1uF_16V_2  [CSC_100X050X040_2]  317.91 35.8 0 bottom
C3301  0.1uF_16V_2  [CSC_100X050X040_2]  317.91 34.91 0 bottom
C3302  0.1uF_16V_2  [CSC_100X050X040_2]  317.91 32.24 0 bottom
C3303  0.1uF_16V_2  [CSC_100X050X040_2]  317.91 31.35 0 bottom
C3304  0.1uF_16V_2  [CSC_100X050X040_2]  317.91 29.58 0 bottom
C3305  0.1uF_16V_2  [CSC_100X050X040_2]  317.91 30.47 0 bottom
C3306  0.1uF_16V_2  [CSC_100X050X040_2]  317.91 33.13 0 bottom
C3307  0.1uF_16V_2  [CSC_100X050X040_2]  317.91 34.02 0 bottom
C3308  1uF_6.3V_2  [CSC_100X050X040_2]  316.52 23.48 180 top
C3310  10uF_6.3V_3  [CSC_160X080X080_2]  316.52 24.5 180 top
C3311  1uF_6.3V_2  [CSC_100X050X040_2]  316.01 37.45 0 top
C3357  1uF_6.3V_2  [CSC_100X050X040_2]  38.64 66.79 270 bottom
C3501  10pF_50V_2_DY  [CSC_100X050X040_2]  123.73 154.67 90 bottom
C3502  0.1uF_16V_2  [CSC_100X050X040_2]  125.64 154.8 90 bottom
C3503  0.1uF_16V_2  [CSC_100X050X040_2]  127.54 147.43 90 top
C3504  0.1uF_16V_2  [CSC_100X050X040_2]  125.38 147.43 270 top
C3506  0.1uF_16V_2  [CSC_100X050X040_2]  121.83 147.43 90 top
C3600  0.1uF_25V_2  [CSC_100X050X040_2]  318.04 127.87 270 top
C3601  0.1uF_25V_2  [CSC_100X050X040_2]  318.93 127.87 270 top
C3602  0.01uF_50V_2  [CSC_100X050X040_2]  320.71 126.99 180 top
C4100  1uF_6.3V_2  [CSC_100X050X040_2]  200.44 136.89 0 top
C4101  1uF_6.3V_2  [CSC_100X050X040_2]  200.44 140.19 0 top
C4102  1uF_6.3V_2  [CSC_100X050X040_2]  200.44 139.18 0 top
C4103  1uF_6.3V_2  [CSC_100X050X040_2]  200.44 137.91 0 top
C4104  0.1uF_16V_2  [CSC_100X050X040_2]  200.44 134.22 180 top
C4105  2.2uF_6.3V_2  [CSC_100X050X040_2]  200.44 133.34 180 top
C4106  330uF_2.5V  [CSTJB_350X280X200_2_300]  227.62 130.92 270 top
C4107  10uF_6.3V_3  [CSC_160X080X080_2]  230.66 130.67 270 top
C4108  1uF_6.3V_2  [CSC_100X050X040_2]  231.68 130.67 270 top
C4109  10uF_6.3V_3  [CSC_160X080X080_2]  233.69 135.62 90 top
C4110  0.1uF_16V_2  [CSC_100X050X040_2]  221.9 141.97 180 top
C4111  2.2uF_6.3V_2  [CSC_100X050X040_2]  221.9 142.86 180 top
C4112  1uF_6.3V_2  [CSC_100X050X040_2]  234.73 135.37 90 top
C4113  10uF_6.3V_3  [CSC_160X080X080_2]  238.67 142.2 0 top
C4114  1uF_6.3V_2  [CSC_100X050X040_2]  231.43 143.62 0 top
C4115  10uF_6.3V_3  [CSC_160X080X080_2]  229.27 143.5 180 top
C4116  1uF_6.3V_2  [CSC_100X050X040_2]  238.67 143.22 0 top
C4117  10uF_6.3V_3  [CSC_160X080X080_2]  223.93 145.15 0 top
C4118  10uF_6.3V_3  [CSC_160X080X080_2]  226.85 143.5 180 top
C4119  0.1uF_16V_2  [CSC_100X050X040_2]  263.18 136.38 180 top
C4120  2.2uF_6.3V_2  [CSC_100X050X040_2]  263.18 137.27 180 top
C4121  0.022uF_16V_2  [CSC_100X050X040_2]  249.59 143.37 270 top
C4122  0.022uF_16V_2  [CSC_100X050X040_2]  189.9 146.04 0 top
C4124  0.022uF_16V_2  [CSC_100X050X040_2]  227.36 102.09 0 top
C4125  1uF_6.3V_2  [CSC_100X050X040_2]  121.83 137.15 180 top
C4126  1uF_6.3V_2  [CSC_100X050X040_2]  121.83 136.26 180 top
C4127  1uF_6.3V_2  [CSC_100X050X040_2]  121.19 140.96 180 top
C4128  1uF_6.3V_2  [CSC_100X050X040_2]  121.19 140.07 180 top
C4129  0.1uF_16V_2  [CSC_100X050X040_2]  124.49 131.81 180 top
C4130  2.2uF_6.3V_2  [CSC_100X050X040_2]  124.49 130.8 180 top
C4131  330uF_2.5V_DY  [CSTJB_350X280X200_2_300]  146.59 142.99 180 top
C4132  10uF_6.3V_3  [CSC_160X080X080_2]  154.08 134.61 90 top
C4133  10uF_6.3V_3  [CSC_160X080X080_2]  161.2 142.61 270 top
C4134  10uF_6.3V_3  [CSC_160X080X080_2]  153.32 141.97 270 top
C4135  0.1uF_16V_2  [CSC_100X050X040_2]  161.58 135.24 90 top
C4136  0.1uF_16V_2  [CSC_100X050X040_2]  152.31 142.23 270 top
C4137  2.2uF_6.3V_2  [CSC_100X050X040_2]  144.81 146.54 90 bottom
C4138  0.1uF_16V_2  [CSC_100X050X040_2]  145.7 146.54 90 bottom
C4139  0.1uF_16V_2  [CSC_100X050X040_2]  152.94 134.61 90 top
C4140  10uF_6.3V_3  [CSC_160X080X080_2]  145.96 135.62 90 top
C4141  10uF_6.3V_3  [CSC_160X080X080_2]  158.27 142.48 270 top
C4142  0.1uF_16V_2  [CSC_100X050X040_2]  162.21 142.61 270 top
C4143  10uF_6.3V_3  [CSC_160X080X080_2]  158.15 135.24 90 top
C4144  0.1uF_16V_2  [CSC_100X050X040_2]  185.45 135.11 270 top
C4145  2.2uF_6.3V_2  [CSC_100X050X040_2]  184.56 135.11 270 top
C4146  2.2uF_6.3V_2  [CSC_100X050X040_2]  229.65 130.67 270 top
C4147  2.2uF_6.3V_2  [CSC_100X050X040_2]  148.11 135.62 90 top
C4200  CSC0402_DY  [CSC_100X050X040_2]  254.41 142.23 270 top
C4201  CSC0402_DY  [CSC_100X050X040_2]  256.19 142.23 270 top
C4202  CSC0402_DY  [CSC_100X050X040_2]  257.97 142.23 270 top
C4203  CSC0402_DY  [CSC_100X050X040_2]  185.83 145.15 180 top
C4204  CSC0402_DY  [CSC_100X050X040_2]  185.83 146.92 180 top
C4205  CSC0402_DY  [CSC_100X050X040_2]  185.83 142.73 180 top
C4206  CSC0402_DY  [CSC_100X050X040_2]  212.63 144.77 90 top
C4207  CSC0402_DY  [CSC_100X050X040_2]  209.07 144.77 90 top
C4209  CSC0402_DY  [CSC_100X050X040_2]  143.92 146.54 90 bottom
C4210  CSC0402_DY  [CSC_100X050X040_2]  202.09 131.56 0 top
C4211  CSC0402_DY  [CSC_100X050X040_2]  200.44 132.45 180 top
C4212  CSC0402_DY  [CSC_100X050X040_2]  170.34 142.35 180 top
C4213  CSC0402_DY  [CSC_100X050X040_2]  167.93 143.24 180 top
C4214  CSC0402_DY  [CSC_100X050X040_2]  170.34 145.91 180 top
C4411  0.1uF_16V_2  [CSC_100X050X040_2]  48.93 85.84 270 top
C4514  47pF_50V_2  [CSC_100X050X040_2]  225.08 80.5 180 top
C4515  10uF_6.3V_3  [CSC_160X080X080_2]  195.36 103.74 270 bottom
C4516  10uF_6.3V_3  [CSC_160X080X080_2]  194.22 103.74 270 bottom
C4521  22uF_6.3V_5  [CSC_200X125X130_2]  193.96 66.69 0 bottom
C4522  22uF_6.3V_5  [CSC_200X125X130_2]  227.24 63.22 0 bottom
C4525  10uF_6.3V_3  [CSC_160X080X080_2]  193.33 87.23 270 top
C4526  10uF_6.3V_3  [CSC_160X080X080_2]  195.87 87.23 270 top
C4527  10uF_6.3V_3  [CSC_160X080X080_2]  202.85 103.74 90 bottom
C4528  10uF_6.3V_3  [CSC_160X080X080_2]  201.33 103.74 90 bottom
C4529  22uF_6.3V_5  [CSC_200X125X130_2]  193.96 68.29 0 bottom
C4530  22uF_6.3V_5  [CSC_200X125X130_2]  198.79 63.49 0 bottom
C4531  22uF_6.3V_5  [CSC_200X125X130_2]  194.47 78.98 0 top
C4532  22uF_6.3V_5  [CSC_200X125X130_2]  208.44 65.09 0 bottom
C4533  22uF_6.3V_5  [CSC_200X125X130_2]  203.61 68.29 0 bottom
C4534  22uF_6.3V_5  [CSC_200X125X130_2]  227.24 61.61 0 bottom
C4535  22uF_6.3V_5  [CSC_200X125X130_2]  199.3 78.98 0 top
C4536  22uF_6.3V_5  [CSC_200X125X130_2]  198.79 66.69 0 bottom
C4537  22uF_6.3V_5  [CSC_200X125X130_2]  208.44 63.49 0 bottom
C4538  22uF_6.3V_5  [CSC_200X125X130_2]  193.96 63.49 0 bottom
C4539  22uF_6.3V_5  [CSC_200X125X130_2]  198.79 65.09 0 bottom
C4540  22uF_6.3V_5  [CSC_200X125X130_2]  203.61 66.69 0 bottom
C4542  22uF_6.3V_5  [CSC_200X125X130_2]  208.44 66.69 0 bottom
C4544  22uF_6.3V_5  [CSC_200X125X130_2]  193.96 65.09 0 bottom
C4545  22uF_6.3V_5  [CSC_200X125X130_2]  225.84 63.87 0 top
C4547  22uF_6.3V_5  [CSC_200X125X130_2]  203.61 63.49 0 bottom
C4548  22uF_6.3V_5  [CSC_200X125X130_2]  203.61 65.09 0 bottom
C4549  22uF_6.3V_5  [CSC_200X125X130_2]  225.84 62.22 0 top
C4555  4.7uF_6.3V_3  [CSC_160X080X080_2]  225.33 75.3 0 top
C4559  22uF_6.3V_5  [CSC_200X125X130_2]  198.79 68.29 0 bottom
C4560  22uF_6.3V_5  [CSC_200X125X130_2]  225.84 65.52 0 top
C4561  22uF_6.3V_5  [CSC_200X125X130_2]  225.84 67.17 0 top
C4590  10uF_6.3V_3_DY  [CSC_160X080X080_2]  189.51 85.71 0 top
C4700  22uF_6.3V_5  [CSC_200X125X130_2]  189.51 87.36 0 top
C4701  1uF_6.3V_2  [CSC_100X050X040_2]  186.6 89.14 90 top
C4709  0.1uF_16V_2  [CSC_100X050X040_2]  147.1 102.98 0 bottom
C4710  1uF_6.3V_2  [CSC_100X050X040_2]  147.1 103.87 0 bottom
C4712  0.1uF_16V_2  [CSC_100X050X040_2]  158.45 90.64 0 bottom
C4714  1uF_6.3V_2  [CSC_100X050X040_2]  186.34 87.23 270 top
C4716  1uF_6.3V_2  [CSC_100X050X040_2]  180.25 88.38 180 top
C4717  0.1uF_16V_2  [CSC_100X050X040_2]  181.64 81.86 90 top
C4718  1uF_6.3V_2  [CSC_100X050X040_2]  184.44 79.61 0 top
C4719  1uF_6.3V_2  [CSC_100X050X040_2]  187.87 81.65 90 top
C4720  1uF_6.3V_2  [CSC_100X050X040_2]  186.34 81.65 90 top
C4721  1uF_6.3V_2  [CSC_100X050X040_2]  184.69 81.52 270 top
C4723  1uF_6.3V_2  [CSC_100X050X040_2]  185.96 76.06 90 top
C4724  1uF_6.3V_2  [CSC_100X050X040_2]  185.83 70.34 270 bottom
C4728  1uF_6.3V_2  [CSC_100X050X040_2]  178.72 87.74 270 top
C4729  22uF_6.3V_5_DY  [CSC_200X125X130_2]  172.77 108.38 180 top
C4730  1uF_6.3V_2  [CSC_100X050X040_2]  173.51 86.85 270 top
C4746  1uF_6.3V_2  [CSC_100X050X040_2]  181.01 85.58 270 top
C4751  10uF_6.3V_3  [CSC_160X080X080_2]  188.25 89.14 0 top
C4753  0.1uF_16V_2  [CSC_100X050X040_2]  158.4 80.57 180 top
C4754  10uF_6.3V_3  [CSC_160X080X080_2]  186.6 74.28 0 top
C4755  10uF_6.3V_3  [CSC_160X080X080_2]  158.4 63.87 90 bottom
C4758  1uF_6.3V_2  [CSC_100X050X040_2]  181.9 86.47 90 top
C4760  1uF_6.3V_2_DY  [CSC_100X050X040_2]  179.74 78.09 180 top
C4761  1uF_6.3V_2  [CSC_100X050X040_2]  179.36 80 0 top
C4762  1uF_6.3V_2  [CSC_100X050X040_2]  153.82 81.03 180 top
C4763  0.1uF_16V_2  [CSC_100X050X040_2]  182.66 79.61 0 top
C4764  1uF_6.3V_2  [CSC_100X050X040_2]  145.45 102.98 0 bottom
C4765  0.1uF_16V_2  [CSC_100X050X040_2]  180.37 81.9 180 top
C4766  1uF_6.3V_2  [CSC_100X050X040_2]  147.1 102.09 0 bottom
C4767  18pF_50V_2  [CSC_100X050X040_2]  164.5 103.49 180 bottom
C4768  1uF_6.3V_2  [CSC_100X050X040_2]  144.94 97.9 0 bottom
C4785  22uF_6.3V_5  [CSC_200X125X130_2]  163.23 63.49 0 bottom
C4786  22uF_6.3V_5  [CSC_200X125X130_2]  166.15 63.49 180 bottom
C4787  10uF_6.3V_3_DY  [CSC_160X080X080_2]  190.04 83.45 0 top
C4788  18pF_50V_2  [CSC_100X050X040_2]  164.5 100.52 180 bottom
C4789  1uF_6.3V_2  [CSC_100X050X040_2]  189.7 84.45 0 top
C4790  22uF_6.3V_5  [CSC_200X125X130_2]  169.7 63.45 0 bottom
C4792  22uF_6.3V_5  [CSC_200X125X130_2]  172.63 63.45 180 bottom
C4818  0.1uF_16V_2  [CSC_100X050X040_2]  183.03 60.65 270 top
C4819  0.1uF_16V_2  [CSC_100X050X040_2]  183.95 60.65 270 top
C4820  0.1uF_16V_2  [CSC_100X050X040_2]  184.06 65.14 270 bottom
C4821  0.1uF_16V_2  [CSC_100X050X040_2]  184.94 65.14 270 bottom
C4822  0.1uF_16V_2  [CSC_100X050X040_2]  192.44 61.07 180 top
C4823  0.1uF_16V_2  [CSC_100X050X040_2]  192.44 60.18 180 top
C4826  15pF_50V_2  [CSC_100X050X040_2]  188.01 67.42 180 bottom
C4828  15pF_50V_2  [CSC_100X050X040_2]  189.61 67.42 0 bottom
C4831  0.1uF_16V_2  [CSC_100X050X040_2]  186.69 60.65 90 top
C4832  0.1uF_16V_2  [CSC_100X050X040_2]  185.78 60.65 90 top
C4833  0.1uF_16V_2  [CSC_100X050X040_2]  184.86 60.65 90 top
C4834  0.1uF_16V_2  [CSC_100X050X040_2]  187.61 60.65 90 top
C4920  0.15uF_10V_2  [CSC_100X050X040_2]  241.97 85.58 270 top
C4935  22uF_6.3V_5  [CSC_200X125X130_2]  187.36 83.3 0 top
C4937  0.1uF_16V_2_DY  [CSC_100X050X055_2]  240.32 87.74 0 top
C4943  0.1uF_16V_2  [CSC_100X050X040_2]  163.74 67.3 270 bottom
C4990  10uF_6.3V_3  [CSC_160X080X080_2]  200.18 103.74 90 bottom
C5009  0.1uF_16V_2  [CSC_100X050X040_2]  111.27 95.22 90 bottom
C5010  1000PF_50V_2  [CSC_100X050X055_2]  197.77 133.21 0 top
C5301  0.1uF_16V_2  [CSC_100X050X040_2]  277.35 71.74 0 bottom
C5302  0.1uF_16V_2  [CSC_100X050X040_2]  277.35 72.63 0 bottom
C5303  0.1uF_16V_2  [CSC_100X050X040_2]  275.16 72.6 0 bottom
C5304  0.1uF_16V_2  [CSC_100X050X040_2]  275.16 73.49 0 bottom
C5305  0.1uF_16V_2  [CSC_100X050X040_2]  277.4 74.03 0 bottom
C5306  0.1uF_16V_2  [CSC_100X050X040_2]  277.4 74.92 0 bottom
C5307  0.1uF_16V_2  [CSC_100X050X040_2]  275.24 75.6 0 bottom
C5308  0.1uF_16V_2  [CSC_100X050X040_2]  275.24 76.49 0 bottom
C5309  0.1uF_16V_2  [CSC_100X050X040_2]  280.19 70.47 270 top
C5310  0.01uF_50V_2  [CSC_100X050X040_2]  280.85 66.54 270 bottom
C5311  0.1uF_16V_2  [CSC_100X050X040_2]  285.91 66.53 270 bottom
C5312  0.01uF_50V_2  [CSC_100X050X040_2]  285.91 79.11 90 bottom
C5313  0.1uF_16V_2  [CSC_100X050X040_2]  281.08 80.5 90 bottom
C5314  2.2uF_6.3V_2_DY  [CSC_100X050X040_2]  277.53 77.46 180 bottom
C5398  0.1uF_16V_2  [CSC_100X050X040_2]  281.97 80.5 270 bottom
C5399  0.1uF_16V_2  [CSC_100X050X040_2]  282.86 80.5 270 bottom
C5401  0.1uF_16V_2  [CSC_100X050X040_2]  260.51 70.85 0 bottom
C5402  0.1uF_16V_2  [CSC_100X050X040_2]  260.51 71.74 0 bottom
C5403  0.1uF_16V_2  [CSC_100X050X040_2]  261.02 72.88 0 bottom
C5404  0.1uF_16V_2  [CSC_100X050X040_2]  261.02 73.77 0 bottom
C5409  0.1uF_16V_2  [CSC_100X050X040_2]  260.51 69.96 180 bottom
C5410  0.01uF_50V_2  [CSC_100X050X040_2]  265.89 66.66 270 bottom
C5411  0.1uF_16V_2  [CSC_100X050X040_2]  270.16 68.82 0 bottom
C5412  0.01uF_50V_2  [CSC_100X050X040_2]  271.46 77.37 0 bottom
C5413  0.1uF_16V_2  [CSC_100X050X040_2]  264.7 80.5 90 bottom
C5414  2.2uF_6.3V_2_DY  [CSC_100X050X040_2]  262.67 75.3 180 bottom
C5450  22UF_6.3V_3  [CSC_160X080X090_2]  274.48 80.12 90 bottom
C5498  0.1uF_16V_2  [CSC_100X050X040_2]  265.59 80.5 270 bottom
C5499  0.1uF_16V_2  [CSC_100X050X040_2]  266.48 80.5 270 bottom
C6000  10UF_25V_5  [CSC_200X125X140_2]  272.32 138.54 180 bottom
C6001  10UF_25V_5  [CSC_200X125X140_2]  272.32 136.76 180 bottom
C6002  CSC0805_DY  [CSC_200X125X130_2]  272.32 140.32 180 bottom
C6010  10UF_25V_5  [CSC_200X125X140_2]  274.48 118.07 0 bottom
C6011  10UF_25V_5  [CSC_200X125X140_2]  274.48 116.44 0 bottom
C6015  0.047uF_16V_2  [CSC_100X050X040_2]  288.32 122.92 90 top
C6016  100pF_50V_2  [CSC_100X050X040_2]  309.4 140.96 270 top
C6017  1000PF_50V_2  [CSC_100X050X055_2]  306.23 140.07 0 top
C6018  100pF_50V_2  [CSC_100X050X040_2]  303.69 142.99 90 top
C6019  0.1uF_16V_2  [CSC_100X050X040_2]  302.8 142.99 90 top
C6020  1000PF_50V_2  [CSC_100X050X055_2]  310.42 140.96 270 top
C6021  0.1uF_25V_2  [CSC_100X050X040_2]  282.23 128.38 90 top
C6022  100pF_50V_2  [CSC_100X050X040_2]  287.56 131.68 90 top
C6023  0.1uF_16V_2  [CSC_100X050X040_2]  281.34 127.49 90 top
C6024  0.1uF_25V_2  [CSC_100X050X040_2]  282.23 126.73 270 top
C6025  1uF_10V_2  [CSC_100X050X040_2]  286.16 122.92 270 top
C6027  1uF_25V_3  [CSC_160X080X080_2]  289.82 122.59 270 top
C6028  0.1uF_16V_2  [CSC_100X050X040_2]  292.46 125.93 270 top
C6029  1uF_25V_3  [CSC_160X080X080_2]  291.44 127.2 270 top
C6030  CSC0402_DY  [CSC_100X050X040_2]  291.44 125.17 270 top
C6031  0.01uF_50V_2  [CSC_100X050X040_2]  283.5 128.89 180 top
C6032  0.01uF_50V_2  [CSC_100X050X040_2]  285.15 131.68 90 top
C6049  100pF_50V_2  [CSC_100X050X040_2]  286.67 131.68 90 top
C6100  100uF_6.3V  [CS_730X430X210_2]  188.93 156.12 180 bottom
C6101  22uF_6.3V_5  [CSC_200X125X130_2]  188.86 152.99 180 bottom
C6109  0.1uF_16V_2  [CSC_100X050X040_2]  202.47 151.8 180 bottom
C6110  10UF_25V_5  [CSC_200X125X140_2]  208.69 154.16 270 bottom
C6111  4.7uF_25V_5  [CSC_200X125X130_2]  207.04 154.16 270 bottom
C6115  0.1uF_16V_2  [CSC_100X050X040_2]  201.84 158.23 270 bottom
C6120  2.2uF_10V_3  [CSC_160X080X080_2]  234.56 146.92 270 bottom
C6121  2.2uF_10V_3  [CSC_160X080X080_2]  203.87 150.51 270 bottom
C6122  1uF_6.3V_2  [CSC_100X050X040_2]  204.88 158.99 0 bottom
C6150  100uF_6.3V  [CS_730X430X210_2]  225.99 155.49 180 bottom
C6151  22uF_6.3V_5  [CSC_200X125X130_2]  228.7 152.37 180 bottom
C6152  22uF_6.3V_5  [CSC_200X125X130_2]  228.69 150.77 180 bottom
C6156  0.1uF_16V_2  [CSC_100X050X040_2]  222.36 149.18 90 bottom
C6157  0.1uF_16V_2  [CSC_100X050X040_2]  217.34 150.76 90 bottom
C6158  0.1uF_16V_2  [CSC_100X050X040_2]  222.41 151.18 90 bottom
C6159  0.22uF_25V_3  [CSC_160X080X080_2]  220.74 149.01 180 bottom
C6160  10UF_25V_5  [CSC_200X125X140_2]  243.44 147.03 270 bottom
C6161  4.7uF_25V_5  [CSC_200X125X130_2]  241.77 147.03 270 bottom
C6165  0.1uF_16V_2  [CSC_100X050X040_2]  243.24 150.73 90 bottom
C6166  220pF_50V_2_DY  [CSC_100X050X040_2]  233.49 150.46 180 bottom
C6169  0.1uF_16V_2  [CSC_100X050X040_2]  234.29 149.06 270 bottom
C6172  1uF_6.3V_2  [CSC_100X050X040_2]  241.59 149.21 0 bottom
C6200  22uF_6.3V_5  [CSC_200X125X130_2]  167.21 158.39 0 bottom
C6201  22uF_6.3V_5  [CSC_200X125X130_2]  167.2 153.53 0 bottom
C6202  22uF_6.3V_5  [CSC_200X125X130_2]  167.21 151.9 0 bottom
